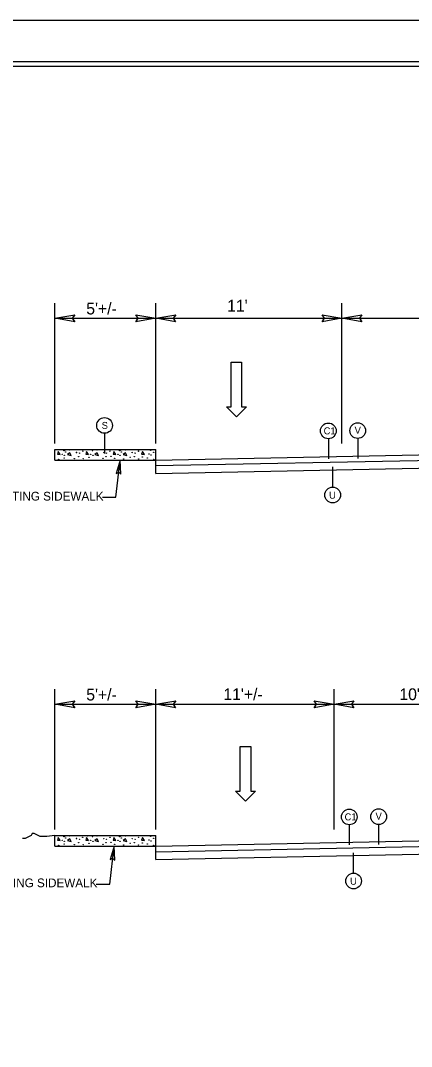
# Model space of a CAD drawing. Extents: x 1022283 to 1026986, y 174822 to 180471.
# Drawn here: x 1023139 to 1023671, y 176176 to 177572 of the extents above; entities that cross this region are included whole.
import ezdxf

# ---------------------------------------------------------------- set-up
doc = ezdxf.new("R2010")
doc.units = 0
for name, color, linetype in [('Default', 7, 'Continuous'), ('Prop Dimension', 7, 'Continuous'), ('Prop Lane Arrow CELL', 7, 'Continuous'), ('Prop Terminator CELL', 7, 'Continuous'), ('Sheet Cutting Line CELL', 7, 'Continuous'), ('Sheet Plot Border Inside CELL', 7, 'Continuous'), ('Sheet Plot Border Outside CELL', 7, 'Continuous'), ('Sheet Typical CELL', 7, 'Continuous'), ('Typical Curb CELL', 7, 'Continuous'), ('Typical ID Circle CELL', 7, 'Continuous'), ('Typical Slope Point Local CELL', 7, 'Continuous'), ('Typical Text General CELL', 7, 'Continuous'), ('Typical Text ID Circle CELL', 7, 'Continuous')]:
    doc.layers.add(name, color=color, linetype=linetype)

# ---------------------------------------------------------------- blocks, each defined once
blk = doc.blocks.new('Lane Arrow Through')
at = {"layer": 'Prop Lane Arrow CELL'}
for p, q in [((-17.15, 1.6), (-3.15, 1.6)), ((-17.15, -1.7), (-17.15, 1.6)), ((-3.15, 1.6), (-3.15, 3.1)), ((-3.15, 3.1), (0, 0)), ((0, 0), (-3.15, -3.2)), ((-3.15, -1.7), (-17.15, -1.7)), ((-3.15, -3.2), (-3.15, -1.7))]:
    blk.add_line(p, q, dxfattribs=at)
blk = doc.blocks.new('Terminator')
at = {"layer": 'Prop Terminator CELL'}
blk.add_lwpolyline([(-9, 1.55), (0, 0), (-9.05, -1.6), (-7.9, 0)], close=True, dxfattribs=at)

msp = doc.modelspace()

# ---------------------------------------------------------------- linework, layer by layer
at = {"layer": 'Default'}
for p, q in [((1023185.5, 176996.9), (1023185.5, 177187.7)), ((1023322.8, 176996.9), (1023322.8, 177187.7)), ((1023576.4, 176996.9), (1023576.4, 177187.7)), ((1023185.5, 177167.2), (1023322.8, 177167.2)), ((1023185.5, 177167.2), (1023322.8, 177167.2)), ((1023322.8, 177167.2), (1023576.4, 177167.2)), ((1023576.4, 177167.2), (1023830.5, 177167.2)), ((1023185.5, 176996.9), (1023185.5, 177152.9)), ((1023185.5, 176996.9), (1023185.5, 177152.9)), ((1023185.5, 176471.5), (1023185.5, 176662.3)), ((1023322.8, 176471.5), (1023322.8, 176662.3)), ((1023565.6, 176471.5), (1023565.6, 176662.3)), ((1023185.5, 176641.8), (1023322.8, 176641.8)), ((1023185.5, 176641.8), (1023322.8, 176641.8)), ((1023322.8, 176641.8), (1023830.5, 176641.8)), ((1023185.5, 176471.5), (1023185.5, 176627.5)), ((1023185.5, 176471.5), (1023185.5, 176627.5))]:
    msp.add_line(p, q, dxfattribs=at)
at = {"layer": 'Prop Dimension'}
for p, q in [((1023322.8, 176974.1), (1023830.5, 176984.3)), ((1023322.8, 176974.1), (1023830.5, 176984.3)), ((1023268.5, 176923.5), (1023274.3, 176974.1)), ((1023322.8, 176966.6), (1023830.5, 176976.8)), ((1023322.8, 176966.6), (1023830.5, 176976.8)), ((1023322.8, 176956), (1023830.5, 176966.2)), ((1023250.3, 176923.5), (1023268.5, 176923.5)), ((1023260.1, 176397.2), (1023266, 176448.7)), ((1023322.8, 176448.7), (1023830.5, 176458.9)), ((1023322.8, 176448.7), (1023830.5, 176458.9)), ((1023322.8, 176441.2), (1023830.5, 176451.4)), ((1023322.8, 176441.2), (1023830.5, 176451.4)), ((1023322.8, 176430.6), (1023830.5, 176440.8)), ((1023241.9, 176397.2), (1023260.1, 176397.2))]:
    msp.add_line(p, q, dxfattribs=at)
at = {"layer": 'Prop Terminator CELL'}
for points in [[(1023212.5, 177162.5), (1023185.5, 177167.2), (1023212.6, 177172), (1023209.2, 177167.2)], [(1023212.5, 177162.5), (1023185.5, 177167.2), (1023212.6, 177172), (1023209.2, 177167.2)], [(1023295.8, 177171.8), (1023322.8, 177167.2), (1023295.7, 177162.4), (1023299.1, 177167.2)], [(1023295.8, 177171.8), (1023322.8, 177167.2), (1023295.7, 177162.4), (1023299.1, 177167.2)], [(1023349.8, 177162.5), (1023322.8, 177167.2), (1023350, 177172), (1023346.5, 177167.2)], [(1023549.4, 177171.8), (1023576.4, 177167.2), (1023549.3, 177162.4), (1023552.7, 177167.2)], [(1023603.4, 177162.5), (1023576.4, 177167.2), (1023603.6, 177172), (1023600.1, 177167.2)], [(1023212.5, 176637.1), (1023185.5, 176641.8), (1023212.6, 176646.6), (1023209.2, 176641.8)], [(1023212.5, 176637.1), (1023185.5, 176641.8), (1023212.6, 176646.6), (1023209.2, 176641.8)], [(1023295.8, 176646.4), (1023322.8, 176641.8), (1023295.7, 176637), (1023299.1, 176641.8)], [(1023295.8, 176646.4), (1023322.8, 176641.8), (1023295.7, 176637), (1023299.1, 176641.8)], [(1023349.8, 176637.1), (1023322.8, 176641.8), (1023350, 176646.6), (1023346.5, 176641.8)], [(1023538.6, 176646.4), (1023565.6, 176641.8), (1023538.5, 176637), (1023541.9, 176641.8)], [(1023592.6, 176637.1), (1023565.6, 176641.8), (1023592.8, 176646.6), (1023589.3, 176641.8)]]:
    msp.add_lwpolyline(points, close=True, dxfattribs=at)
at = {"layer": 'Sheet Cutting Line CELL'}
msp.add_line((1026493.2, 177572.5), (1022283.2, 177572.5), dxfattribs=at)
at = {"layer": 'Sheet Plot Border Inside CELL'}
msp.add_lwpolyline([(1026482, 177516.3), (1022315.7, 177516.3), (1022315.7, 174878.6), (1026482, 174878.6)], close=True, dxfattribs=at)
at = {"layer": 'Sheet Plot Border Outside CELL'}
msp.add_lwpolyline([(1026493.2, 177572.5), (1022283.2, 177572.5), (1022283.2, 174822.5), (1026493.2, 174822.5)], close=True, dxfattribs=at)
at = {"layer": 'Sheet Typical CELL'}
msp.add_lwpolyline([(1026450.7, 177510), (1022700.7, 177510), (1022700.7, 174885), (1026450.7, 174885)], close=True, dxfattribs=at)
at = {"layer": 'Typical Curb CELL'}
for p, q in [((1023185.5, 176988.7), (1023322.8, 176988.7)), ((1023185.5, 176974.1), (1023185.5, 176988.7)), ((1023185.5, 176988.7), (1023322.8, 176988.7)), ((1023185.5, 176974.1), (1023185.5, 176988.7)), ((1023190, 176985.7), (1023188.9, 176982.2)), ((1023190, 176985.7), (1023188.9, 176982.2)), ((1023188.9, 176982.2), (1023192.6, 176982)), ((1023188.9, 176982.2), (1023192.6, 176982)), ((1023192.6, 176982), (1023190, 176985.7)), ((1023192.6, 176982), (1023190, 176985.7)), ((1023205.7, 176984), (1023202.5, 176981.7)), ((1023205.7, 176984), (1023202.5, 176981.7)), ((1023202.5, 176981.7), (1023207.6, 176980.4)), ((1023202.5, 176981.7), (1023207.6, 176980.4)), ((1023207.6, 176980.4), (1023205.7, 176984)), ((1023207.6, 176980.4), (1023205.7, 176984)), ((1023228.7, 176985.7), (1023227.6, 176982.2)), ((1023228.7, 176985.7), (1023227.6, 176982.2)), ((1023227.6, 176982.2), (1023231.4, 176982)), ((1023227.6, 176982.2), (1023231.4, 176982)), ((1023231.4, 176982), (1023228.7, 176985.7)), ((1023231.4, 176982), (1023228.7, 176985.7)), ((1023242.9, 176984), (1023239.7, 176981.7)), ((1023242.9, 176984), (1023239.7, 176981.7)), ((1023239.7, 176981.7), (1023244.8, 176980.4)), ((1023239.7, 176981.7), (1023244.8, 176980.4)), ((1023244.8, 176980.4), (1023242.9, 176984)), ((1023244.8, 176980.4), (1023242.9, 176984)), ((1023265.8, 176985.7), (1023264.8, 176982.2)), ((1023265.8, 176985.7), (1023264.8, 176982.2)), ((1023264.8, 176982.2), (1023268.5, 176982)), ((1023264.8, 176982.2), (1023268.5, 176982)), ((1023268.5, 176982), (1023265.8, 176985.7)), ((1023268.5, 176982), (1023265.8, 176985.7)), ((1023281.6, 176984), (1023278.4, 176981.7)), ((1023281.6, 176984), (1023278.4, 176981.7)), ((1023278.4, 176981.7), (1023283.5, 176980.4)), ((1023278.4, 176981.7), (1023283.5, 176980.4)), ((1023283.5, 176980.4), (1023281.6, 176984)), ((1023283.5, 176980.4), (1023281.6, 176984)), ((1023304.6, 176985.7), (1023303.5, 176982.2)), ((1023304.6, 176985.7), (1023303.5, 176982.2)), ((1023303.5, 176982.2), (1023307.3, 176982)), ((1023303.5, 176982.2), (1023307.3, 176982)), ((1023307.3, 176982), (1023304.6, 176985.7)), ((1023307.3, 176982), (1023304.6, 176985.7)), ((1023322.8, 176956), (1023322.8, 176988.7)), ((1023322.8, 176978.3), (1023322.8, 176988.7)), ((1023322.8, 176956), (1023322.8, 176988.7)), ((1023322.8, 176978.3), (1023322.8, 176988.7)), ((1023185.5, 176974.1), (1023322.8, 176974.1)), ((1023322.8, 176957.7), (1023322.8, 176975.6)), ((1023322.8, 176957.7), (1023322.8, 176975.6)), ((1023185.5, 176463.3), (1023322.8, 176463.3)), ((1023185.5, 176448.7), (1023185.5, 176463.3)), ((1023185.5, 176463.3), (1023322.8, 176463.3)), ((1023185.5, 176448.7), (1023185.5, 176463.3)), ((1023322.8, 176430.6), (1023322.8, 176463.3)), ((1023322.8, 176452.9), (1023322.8, 176463.3)), ((1023322.8, 176430.6), (1023322.8, 176463.3)), ((1023322.8, 176452.9), (1023322.8, 176463.3)), ((1023185.5, 176448.7), (1023322.8, 176448.7)), ((1023190, 176460.3), (1023188.9, 176456.8)), ((1023190, 176460.3), (1023188.9, 176456.8)), ((1023188.9, 176456.8), (1023192.6, 176456.6)), ((1023188.9, 176456.8), (1023192.6, 176456.6)), ((1023192.6, 176456.6), (1023190, 176460.3)), ((1023192.6, 176456.6), (1023190, 176460.3)), ((1023205.7, 176458.6), (1023202.5, 176456.3)), ((1023205.7, 176458.6), (1023202.5, 176456.3)), ((1023202.5, 176456.3), (1023207.6, 176455)), ((1023202.5, 176456.3), (1023207.6, 176455)), ((1023207.6, 176455), (1023205.7, 176458.6)), ((1023207.6, 176455), (1023205.7, 176458.6)), ((1023228.7, 176460.3), (1023227.6, 176456.8)), ((1023228.7, 176460.3), (1023227.6, 176456.8)), ((1023227.6, 176456.8), (1023231.4, 176456.6)), ((1023227.6, 176456.8), (1023231.4, 176456.6)), ((1023231.4, 176456.6), (1023228.7, 176460.3)), ((1023231.4, 176456.6), (1023228.7, 176460.3)), ((1023242.9, 176458.6), (1023239.7, 176456.3)), ((1023242.9, 176458.6), (1023239.7, 176456.3)), ((1023239.7, 176456.3), (1023244.8, 176455)), ((1023239.7, 176456.3), (1023244.8, 176455)), ((1023244.8, 176455), (1023242.9, 176458.6)), ((1023244.8, 176455), (1023242.9, 176458.6)), ((1023265.8, 176460.3), (1023264.8, 176456.8)), ((1023265.8, 176460.3), (1023264.8, 176456.8)), ((1023264.8, 176456.8), (1023268.5, 176456.6)), ((1023264.8, 176456.8), (1023268.5, 176456.6)), ((1023268.5, 176456.6), (1023265.8, 176460.3)), ((1023268.5, 176456.6), (1023265.8, 176460.3)), ((1023281.6, 176458.6), (1023278.4, 176456.3)), ((1023281.6, 176458.6), (1023278.4, 176456.3)), ((1023278.4, 176456.3), (1023283.5, 176455)), ((1023278.4, 176456.3), (1023283.5, 176455)), ((1023283.5, 176455), (1023281.6, 176458.6)), ((1023283.5, 176455), (1023281.6, 176458.6)), ((1023304.6, 176460.3), (1023303.5, 176456.8)), ((1023304.6, 176460.3), (1023303.5, 176456.8)), ((1023303.5, 176456.8), (1023307.3, 176456.6)), ((1023303.5, 176456.8), (1023307.3, 176456.6)), ((1023307.3, 176456.6), (1023304.6, 176460.3)), ((1023307.3, 176456.6), (1023304.6, 176460.3)), ((1023322.8, 176432.3), (1023322.8, 176450.2)), ((1023322.8, 176432.3), (1023322.8, 176450.2))]:
    msp.add_line(p, q, dxfattribs=at)
for centre in [(1023191.6, 176988.2), (1023191.6, 176988.2), (1023195.4, 176982), (1023195.4, 176982), (1023197.9, 176987), (1023197.9, 176987), (1023198.1, 176977.1), (1023198.1, 176977.1), (1023198.4, 176980.6), (1023198.4, 176980.6), (1023199.7, 176988.1), (1023199.7, 176988.1), (1023200.2, 176985.1), (1023200.2, 176985.1), (1023205.7, 176988.1), (1023205.7, 176988.1), (1023214.9, 176984.5), (1023214.9, 176984.5), (1023217.7, 176978.9), (1023217.7, 176978.9), (1023218.8, 176983.6), (1023218.8, 176983.6), (1023223.4, 176986.3), (1023223.4, 176986.3), (1023230.3, 176988.2), (1023230.3, 176988.2), (1023231.9, 176978), (1023231.9, 176978), (1023234.2, 176982), (1023234.2, 176982), (1023236.7, 176987), (1023236.7, 176987), (1023237.2, 176980.6), (1023237.2, 176980.6), (1023242.8, 176988.1), (1023242.8, 176988.1), (1023252, 176984.5), (1023252, 176984.5), (1023254.9, 176978.9), (1023254.9, 176978.9), (1023255.9, 176983.6), (1023255.9, 176983.6), (1023260.5, 176986.3), (1023260.5, 176986.3), (1023261.8, 176979.2), (1023261.8, 176979.2), (1023267.4, 176988.2), (1023267.4, 176988.2), (1023271.3, 176982), (1023271.3, 176982), (1023273.8, 176987), (1023273.8, 176987), (1023274.3, 176980.6), (1023274.3, 176980.6), (1023275.6, 176988.1), (1023275.6, 176988.1), (1023276.1, 176985.1), (1023276.1, 176985.1), (1023281.6, 176988.1), (1023281.6, 176988.1), (1023288, 176977.8), (1023288, 176977.8), (1023290.8, 176984.5), (1023290.8, 176984.5), (1023293.6, 176978.9), (1023293.6, 176978.9), (1023294.7, 176983.6), (1023294.7, 176983.6), (1023299.3, 176986.3), (1023299.3, 176986.3), (1023304.5, 176978.4), (1023304.5, 176978.4), (1023306.2, 176988.2), (1023306.2, 176988.2), (1023311.4, 176977.1), (1023311.4, 176977.1), (1023313.5, 176982.6), (1023313.5, 176982.6), (1023316, 176987.5), (1023316, 176987.5), (1023316.5, 176981.2), (1023316.5, 176981.2), (1023320, 176984.9), (1023320, 176984.9), (1023190.7, 176975.2), (1023190.7, 176975.2), (1023211.8, 176976.1), (1023211.8, 176976.1), (1023224, 176976.1), (1023224, 176976.1), (1023250.9, 176976.7), (1023250.9, 176976.7), (1023266.8, 176976.7), (1023266.8, 176976.7), (1023279, 176975.7), (1023279, 176975.7), (1023299.4, 176975.5), (1023299.4, 176975.5), (1023320, 176975.4), (1023320, 176975.4), (1023191.6, 176462.8), (1023191.6, 176462.8), (1023197.9, 176461.6), (1023197.9, 176461.6), (1023199.7, 176462.7), (1023199.7, 176462.7), (1023205.7, 176462.7), (1023205.7, 176462.7), (1023223.4, 176460.9), (1023223.4, 176460.9), (1023230.3, 176462.8), (1023230.3, 176462.8), (1023236.7, 176461.6), (1023236.7, 176461.6), (1023242.8, 176462.7), (1023242.8, 176462.7), (1023260.5, 176460.9), (1023260.5, 176460.9), (1023267.4, 176462.8), (1023267.4, 176462.8), (1023273.8, 176461.6), (1023273.8, 176461.6), (1023275.6, 176462.7), (1023275.6, 176462.7), (1023281.6, 176462.7), (1023281.6, 176462.7), (1023299.3, 176460.9), (1023299.3, 176460.9), (1023306.2, 176462.8), (1023306.2, 176462.8), (1023316, 176462.1), (1023316, 176462.1), (1023190.7, 176449.8), (1023190.7, 176449.8), (1023195.4, 176456.6), (1023195.4, 176456.6), (1023198.1, 176451.7), (1023198.1, 176451.7), (1023198.4, 176455.2), (1023198.4, 176455.2), (1023200.2, 176459.7), (1023200.2, 176459.7), (1023211.8, 176450.7), (1023211.8, 176450.7), (1023214.9, 176459.1), (1023214.9, 176459.1), (1023217.7, 176453.5), (1023217.7, 176453.5), (1023218.8, 176458.2), (1023218.8, 176458.2), (1023224, 176450.7), (1023224, 176450.7), (1023231.9, 176452.6), (1023231.9, 176452.6), (1023234.2, 176456.6), (1023234.2, 176456.6), (1023237.2, 176455.2), (1023237.2, 176455.2), (1023250.9, 176451.3), (1023250.9, 176451.3), (1023252, 176459.1), (1023252, 176459.1), (1023254.9, 176453.5), (1023254.9, 176453.5), (1023255.9, 176458.2), (1023255.9, 176458.2), (1023261.8, 176453.8), (1023261.8, 176453.8), (1023266.8, 176451.3), (1023266.8, 176451.3), (1023271.3, 176456.6), (1023271.3, 176456.6), (1023274.3, 176455.2), (1023274.3, 176455.2), (1023276.1, 176459.7), (1023276.1, 176459.7), (1023279, 176450.3), (1023279, 176450.3), (1023288, 176452.4), (1023288, 176452.4), (1023290.8, 176459.1), (1023290.8, 176459.1), (1023293.6, 176453.5), (1023293.6, 176453.5), (1023294.7, 176458.2), (1023294.7, 176458.2), (1023299.4, 176450.1), (1023299.4, 176450.1), (1023304.5, 176453), (1023304.5, 176453), (1023311.4, 176451.7), (1023311.4, 176451.7), (1023313.5, 176457.2), (1023313.5, 176457.2), (1023316.5, 176455.8), (1023316.5, 176455.8), (1023320, 176459.5), (1023320, 176459.5), (1023320, 176450), (1023320, 176450)]:
    msp.add_circle(centre, 0.249, dxfattribs=at)
at = {"layer": 'Typical ID Circle CELL'}
for p, q in [((1023253.1, 177010.7), (1023253.1, 176983.2)), ((1023557.9, 177003.3), (1023557.9, 176975.7)), ((1023597.9, 177003.7), (1023597.9, 176976.2)), ((1023563.8, 176937.4), (1023563.8, 176964.9)), ((1023586.4, 176477.9), (1023586.4, 176450.3)), ((1023626.4, 176478.3), (1023626.4, 176450.8)), ((1023592.3, 176412), (1023592.3, 176439.5))]:
    msp.add_line(p, q, dxfattribs=at)
for centre in [(1023253.1, 177021.3), (1023557.9, 177013.9), (1023597.9, 177014.3), (1023563.8, 176926.7), (1023586.4, 176488.5), (1023626.4, 176488.9), (1023592.3, 176401.3)]:
    msp.add_circle(centre, 10.7, dxfattribs=at)
at = {"layer": 'Typical Slope Point Local CELL'}
msp.add_lwpolyline([(1023185.5, 176463.3), (1023174.7, 176461.9), (1023172, 176461.9), (1023167.9, 176461.9), (1023165.3, 176461.9), (1023162.6, 176463.3), (1023159.9, 176464.6), (1023157.2, 176466), (1023154.5, 176466), (1023153.1, 176463.3), (1023150.4, 176461.9), (1023147.7, 176460.6), (1023145.1, 176459.2), (1023142.4, 176459.2), (1023141.3, 176459.2)], dxfattribs=at)
msp.add_lwpolyline([(1023185.5, 176463.3), (1023174.7, 176461.9), (1023172, 176461.9), (1023167.9, 176461.9), (1023165.3, 176461.9), (1023162.6, 176463.3), (1023159.9, 176464.6), (1023157.2, 176466), (1023154.5, 176466), (1023153.1, 176463.3), (1023150.4, 176461.9), (1023147.7, 176460.6), (1023145.1, 176459.2), (1023142.4, 176459.2), (1023141.3, 176459.2)], dxfattribs=at)

# ---------------------------------------------------------------- block references
at = {"layer": 'Prop Dimension', "xscale": 2.0767499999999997, "yscale": -2.076749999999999, "rotation": 83.4116733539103}
for p in [(1023274.3, 176974.1), (1023266, 176448.7)]:
    msp.add_blockref('Terminator', p, dxfattribs=at)
at = {"layer": 'Prop Lane Arrow CELL', "xscale": 4.329849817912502, "yscale": 4.3298498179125, "rotation": -89.99999999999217}
for p in [(1023432.9, 177033.1), (1023445.2, 176510.1)]:
    msp.add_blockref('Lane Arrow Through', p, dxfattribs=at)

# ---------------------------------------------------------------- texts
at = {"layer": 'Prop Dimension'}
for s, p in [("5'+/-", (1023228.2, 177172.4)), ("11'", (1023420.1, 177176.3)), ("5'+/-", (1023228.2, 176647)), ("11'+/-", (1023415, 176647.5)), ("10'+/-", (1023654.7, 176647.5))]:
    msp.add_text(s, height=16, dxfattribs=at).set_placement(p)
at = {"layer": 'Typical Text General CELL'}
for p in [(1023090.8, 176919.1), (1023082.4, 176392.8)]:
    msp.add_text('EXISTING SIDEWALK', height=11.898, dxfattribs=at).set_placement(p)
at = {"layer": 'Typical Text ID Circle CELL'}
for s, p in [('S', (1023249.2, 177016.6)), ('V', (1023593.7, 177010)), ('C1', (1023551.5, 177009.2)), ('U', (1023558.9, 176921.6)), ('C1', (1023580, 176483.8)), ('V', (1023622.2, 176484.6)), ('U', (1023587.5, 176396.2))]:
    msp.add_text(s, height=9.53, dxfattribs=at).set_placement(p)

doc.saveas('drawing.dxf')
